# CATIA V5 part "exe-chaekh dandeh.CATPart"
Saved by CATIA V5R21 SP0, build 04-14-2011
Part number: exe-chaekh dandeh
Bounding box of the stored display mesh (mm): x -10 to 10, y -64.967 to 64.967, z -64.967 to 64.967
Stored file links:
  C:\Users\amir\Desktop\exe-chaekh dandeh.CATPart
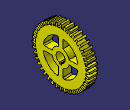
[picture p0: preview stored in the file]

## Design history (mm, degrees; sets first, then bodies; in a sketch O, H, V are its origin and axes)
Body1 (main body)
  Sketch1 on yz-plane, origin (0, 0, 0), H (0, 1, 0), V (0, 0, 1)
    circle A1 centre (0, 0) radius 57.5
    radius A1 = 57.5
  Pad1: profile Sketch1, direction (1, 0, 0), length 10, mirrored extent
  Sketch2 on end face of Pad1, origin (10, 0, 0), H (0, 1, 0), V (0, 0, 1)
    arc A1 centre (0, 0) radius 65 from (2.0645, 64.9672) to (-2.0645, 64.9672) ccw
    arc A2 centre (7.5, 62.0484) radius 10 from (-2.0645, 64.9672) to (-1.3971, 57.483) ccw
    arc A3 centre (-7.5, 62.0484) radius 10 from (2.0645, 64.9672) to (1.3971, 57.483) cw
    point P1 (2.0645, 64.9672)
    point P2 (-2.0645, 64.9672)
    arc A4 centre (0, 0) radius 57.5 from (1.3971, 57.483) to (-1.3971, 57.483) ccw
    point P3 (1.3971, 57.483)
    point P4 (-1.3971, 57.483)
    radius A1 = 65
    radius A3 = 10
    distance A1 A4 = 7.5
    radius A1 = 65 (reference)
    distance P1 P2 = 4.1291
    distance P3 P4 = 2.7941
    symmetry: A2 A3 V
  Pad2: profile Sketch2, direction (-1, 0, 0), length 20
  CircPattern1: of Pad2, instances 40, angular step 9 {= 360.0*1 deg/CircPattern1.AngularNumber}, axis from face of Pad2
  Sketch3 on face of CircPattern1, origin (10, 0, 0), H (0, 1, 0), V (0, 0, 1)
    line L1 (39.6863, 5) -> (19.3649, 5)
    line L2 (5, 19.3649) -> (5, 39.6863)
    arc A1 centre (0, 0) radius 40 from (5, 39.6863) to (39.6863, 5) cw
    point P3 (0, 0)
    arc A2 centre (0, 0) radius 20 from (19.3649, 5) to (5, 19.3649) ccw
    distance H L1 = 5
    distance V L2 = 5
    radius A1 = 40
    radius A2 = 20
    horizontal: L1 H
    vertical: L2 V
    coincidence: P3 O
  Pocket1: profile Sketch3, direction (-1, 0, 0), length 20
  CircPattern2: of Pocket1, instances 4, angular step 90 {= 360.0*1 deg/CircPattern2.AngularNumber}, axis from face of CircPattern1
  Sketch4 on face of CircPattern1, origin (10, 0, 0), H (0, 1, 0), V (0, 0, 1)
    arc A1 centre (0, 0) radius 10.5 from (2.5, -10.198) to (-2.5, -10.198) ccw
    line L1 (-2.5, -10.198) -> (-2.5, -14)
    line L2 (-2.5, -14) -> (2.5, -14)
    line L3 (2.5, -14) -> (2.5, -10.198)
    radius A1 = 10.5
    distance H L2 = 14
    length L2 = 5
    vertical: L1 V, L3 V
    horizontal: L2 H
    symmetry: L3 L1 V
  Pocket2: profile Sketch4, direction (-1, 0, 0), length 20
  Fillet1: radius 2.5, on edge [face of Pocket1 from Sketch3.A1 | face of Pocket1 from Sketch3.L1]; edge [face of Pocket1 from Sketch3.L2 | face of Pocket1 from Sketch3.A1]; edge [face of CircPattern2 | face of CircPattern2] (x6)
